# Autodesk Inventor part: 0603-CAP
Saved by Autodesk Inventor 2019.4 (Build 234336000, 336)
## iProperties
Created: 2021-02
Part Number: 0603-CAP
Material: Generic
Document SubType Name: Modeling
Designer: Administrator
Density: 1 g/cm^3
Appearance: Default
Title: 0603-CAP
Author: Administrator
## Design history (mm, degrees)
feature "Body1"
body "Solid1"
